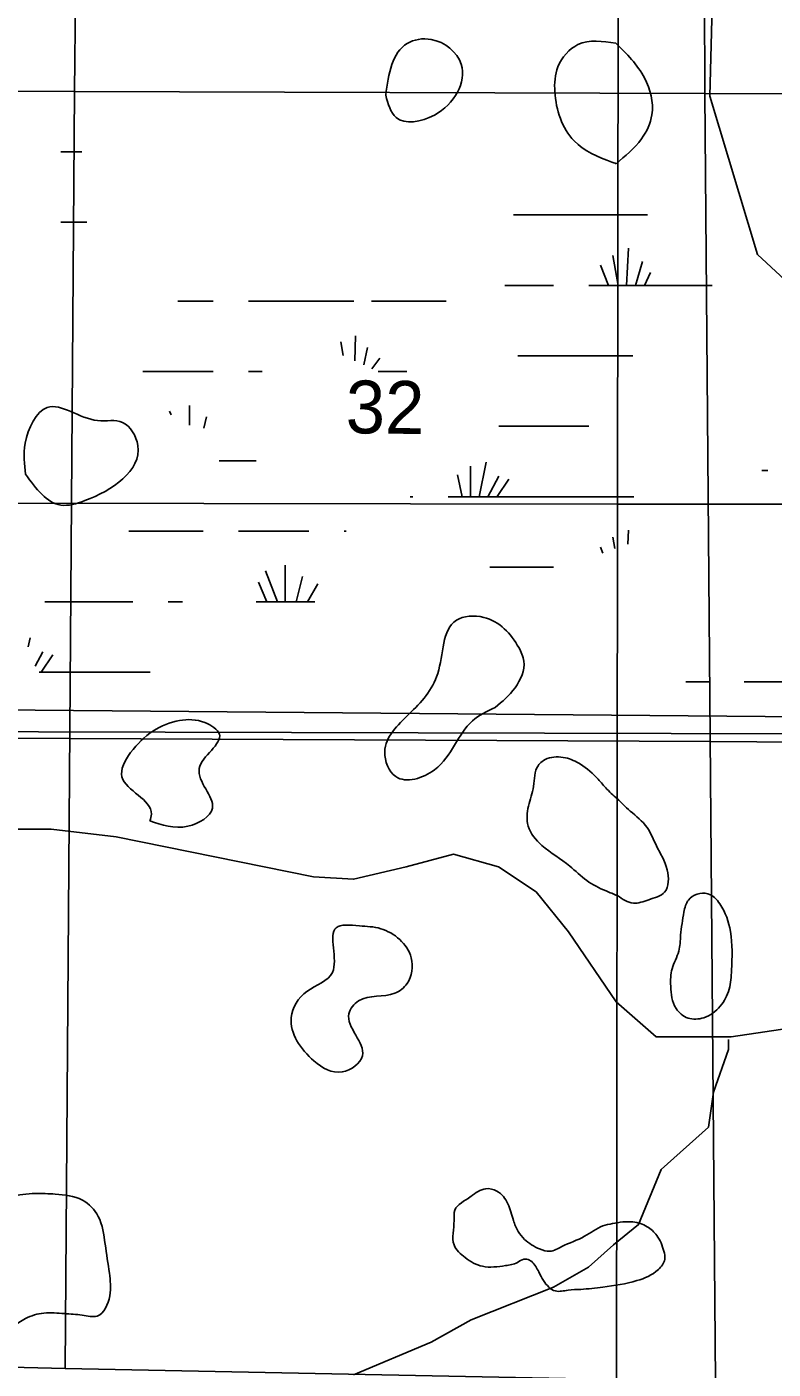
# Model space of a CAD drawing. Extents: x 408847 to 817539, y 923858 to 1151780.
# Drawn here: x 610539 to 616897, y 1007384 to 1018814 of the extents above; entities that cross this region are included whole.
import ezdxf

# ---------------------------------------------------------------- set-up
doc = ezdxf.new("R2010")
doc.units = 0
for name, color, linetype in [('Cities Incorporated Linear Boundaries', 7, 'Continuous'), ('Lakes and Ponds', 7, 'Continuous'), ('Level 43', 7, 'Continuous'), ('Local Roads Paved', 7, 'Continuous'), ('Narrow River Creek and Branch and Slough', 7, 'Continuous'), ('Quad Borders', 7, 'Continuous'), ('Section Lines', 7, 'Continuous'), ('Swamps', 7, 'Continuous')]:
    doc.layers.add(name, color=color, linetype=linetype)

msp = doc.modelspace()

# ---------------------------------------------------------------- linework, layer by layer
at = {"layer": 'Cities Incorporated Linear Boundaries'}
msp.add_line((637441, 1012760), (573420, 1013321), dxfattribs=at)
msp.add_lwpolyline([(605246, 1012826), (637589, 1012739), (637461, 996763)], dxfattribs=at)
at = {"layer": 'Lakes and Ponds'}
msp.add_line((615561, 1012248), (615582, 1012229), dxfattribs=at)
for points in [[(613596, 1018233), (613684, 1018043), (614011, 1018063), (614240, 1018495), (613984, 1018707), (613779, 1018673), (613596, 1018233)], [(615559, 1017649), (615523, 1017662), (615201, 1017844), (615037, 1018260), (615064, 1018474), (615234, 1018663), (615558, 1018675)], [(615558, 1018675), (615801, 1018379), (615864, 1018066), (615775, 1017860), (615559, 1017649)], [(610527, 1015004), (610828, 1014742), (611034, 1014780), (611484, 1015250), (611354, 1015446), (611142, 1015462), (610713, 1015573), (610525, 1015268), (610527, 1015004)], [(614528, 1013019), (614335, 1012905), (614012, 1012488), (613682, 1012430), (613588, 1012641), (613793, 1012961), (614039, 1013307), (614198, 1013762), (614431, 1013786), (614730, 1013528), (614773, 1013413), (614698, 1013186), (614528, 1013019)], [(611587, 1012052), (611911, 1012008), (612120, 1012162), (612008, 1012498), (612179, 1012792), (612056, 1012890), (611840, 1012908), (611423, 1012634), (611349, 1012427), (611600, 1012110), (611587, 1012052)], [(615582, 1012229), (615481, 1012323), (615406, 1012408), (615256, 1012535), (615127, 1012590), (614973, 1012583), (614894, 1012523), (614855, 1012347), (614812, 1012179), (614810, 1012009), (614927, 1011844), (615164, 1011668), (615309, 1011545), (615473, 1011456), (615570, 1011417)], [(615570, 1011417), (615706, 1011352), (615838, 1011382), (615972, 1011446), (615994, 1011636), (615903, 1011841), (615823, 1011997), (615679, 1012137), (615561, 1012248)], [(616137, 1011277), (616109, 1011079), (616093, 1010943), (616036, 1010794), (616024, 1010646), (616070, 1010456), (616172, 1010374), (616306, 1010377), (616446, 1010475), (616522, 1010619), (616543, 1010782), (616533, 1011110), (616443, 1011346), (616340, 1011433), (616175, 1011379), (616137, 1011277)], [(613373, 1011158), (613174, 1011143), (613143, 1010763), (612924, 1010601), (612791, 1010378), (612985, 1010009), (613226, 1009916), (613398, 1010053), (613282, 1010411), (613365, 1010520), (613674, 1010585), (613779, 1010668), (613813, 1010888), (613554, 1011135), (613373, 1011158)], [(614322, 1008856), (614448, 1008921), (614543, 1008901), (614637, 1008793), (614684, 1008651), (614725, 1008557), (614779, 1008489), (614907, 1008408), (614995, 1008388), (615096, 1008428), (615291, 1008516), (615447, 1008604), (615528, 1008624), (615703, 1008638), (615824, 1008597), (615905, 1008523), (615966, 1008388), (615973, 1008320), (615919, 1008233), (615737, 1008138), (615447, 1008084), (615258, 1008064), (615150, 1008057), (615042, 1008050), (614941, 1008138), (614900, 1008212), (614840, 1008300), (614799, 1008320), (614772, 1008320), (614718, 1008293), (614617, 1008266), (614421, 1008260), (614273, 1008334), (614179, 1008442), (614179, 1008651), (614185, 1008739), (614317, 1008852), (614322, 1008856)], [(609791, 1008399), (609740, 1008311), (609683, 1008167), (609672, 1008017), (609749, 1007844), (609984, 1007678), (610142, 1007665), (610302, 1007684), (610527, 1007815), (610683, 1007862), (610859, 1007857), (611011, 1007844), (611139, 1007837), (611245, 1008009), (611242, 1008201), (611206, 1008450), (611147, 1008685), (611012, 1008824), (610780, 1008875), (610612, 1008880), (610400, 1008849), (610169, 1008747), (610041, 1008683), (609912, 1008546), (609791, 1008399)]]:
    msp.add_spline(points, degree=3, dxfattribs=at)
at = {"layer": 'Local Roads Paved'}
for points in [[(617113, 1010298), (616538, 1010213), (616134, 1010213), (615899, 1010213), (615559, 1010511), (615154, 1011108), (614877, 1011449), (614558, 1011662), (614174, 1011769), (613770, 1011662), (613322, 1011556), (612982, 1011577), (611299, 1011918), (610745, 1011982), (610277, 1011982)], [(613322, 1007336), (613983, 1007613), (614323, 1007805), (615026, 1008082), (615324, 1008253), (615537, 1008444), (615750, 1008615), (615942, 1009084), (616347, 1009446), (616389, 1009744), (616517, 1010107), (616517, 1010192)]]:
    msp.add_lwpolyline(points, dxfattribs=at)
at = {"layer": 'Narrow River Creek and Branch and Slough'}
msp.add_lwpolyline([(618154, 1014774), (617887, 1015834), (616765, 1016876), (616357, 1018223), (616454, 1021936)], dxfattribs=at)
at = {"layer": 'Quad Borders'}
for p, q in [((615571, 1014751), (615617, 1060189)), ((574913, 1014812), (615571, 1014751)), ((615526, 969314), (615571, 1014751)), ((615571, 1014751), (656229, 1014731))]:
    msp.add_line(p, q, dxfattribs=at)
at = {"layer": 'Section Lines'}
for p, q in [((616311, 1023460), (616314, 1018246)), ((610984, 1023387), (610946, 1018265)), ((605727, 1018283), (610946, 1018265)), ((610865, 1007391), (610946, 1018265)), ((610946, 1018265), (616314, 1018246)), ((616314, 1018246), (616407, 1007278)), ((605650, 1012780), (610905, 1012754)), ((610905, 1012754), (616361, 1012728)), ((616361, 1012728), (621605, 1012703)), ((605556, 1007500), (610865, 1007391)), ((610865, 1007391), (616407, 1007278))]:
    msp.add_line(p, q, dxfattribs=at)
msp.add_lwpolyline([(616314, 1018248), (621598, 1018242)], dxfattribs=at)
at = {"layer": 'Swamps'}
for p, q in [((615649, 1016613), (615666, 1016929)), ((615493, 1016613), (615427, 1016785)), ((615578, 1016613), (615531, 1016868)), ((615725, 1016613), (615784, 1016817)), ((615802, 1016613), (615851, 1016722)), ((615327, 1016613), (616377, 1016613)), ((611826, 1016479), (612126, 1016479)), ((611826, 1016479), (612126, 1016479)), ((611826, 1016479), (612126, 1016479)), ((612426, 1016479), (613026, 1016479)), ((612426, 1016479), (613026, 1016479)), ((612426, 1016479), (613026, 1016479)), ((613026, 1016479), (613326, 1016479)), ((613026, 1016479), (613326, 1016479)), ((613026, 1016479), (613326, 1016479)), ((611526, 1015879), (612126, 1015879)), ((611526, 1015879), (612126, 1015879)), ((611526, 1015879), (612126, 1015879)), ((614318, 1015072), (614318, 1014813)), ((614451, 1015108), (614392, 1014813)), ((614209, 1014999), (614247, 1014813)), ((614560, 1014987), (614466, 1014812)), ((614644, 1014963), (614545, 1014814)), ((612342, 1014519), (612942, 1014519)), ((612342, 1014519), (612942, 1014519)), ((612572, 1014181), (612675, 1013919)), ((612572, 1014181), (612675, 1013919)), ((612741, 1014230), (612741, 1013919)), ((612741, 1014230), (612741, 1013919)), ((612511, 1014085), (612582, 1013919)), ((612511, 1014085), (612582, 1013919)), ((612886, 1014133), (612832, 1013918)), ((612886, 1014133), (612832, 1013918)), ((610759, 1013468), (610660, 1013319)), ((610759, 1013468), (610660, 1013319)), ((616651, 1013237), (617101, 1013237))]:
    msp.add_line(p, q, dxfattribs=at)
for points in [[(610827, 1017751), (611006, 1017751)], [(610827, 1017751), (611006, 1017751)], [(610827, 1017751), (611006, 1017751)], [(610827, 1017151), (611051, 1017151)], [(610827, 1017151), (611051, 1017151)], [(610827, 1017151), (611051, 1017151)], [(614685, 1017213), (615827, 1017213)], [(614610, 1016613), (615027, 1016613)], [(613476, 1016479), (614110, 1016479)], [(613476, 1016479), (614110, 1016479)], [(613476, 1016479), (614110, 1016479)], [(613233, 1016015), (613214, 1016132)], [(613233, 1016015), (613214, 1016132)], [(613233, 1016015), (613214, 1016132)], [(613334, 1015971), (613338, 1016182)], [(613334, 1015971), (613338, 1016182)], [(613334, 1015971), (613338, 1016182)], [(613411, 1015935), (613442, 1016084)], [(613411, 1015935), (613442, 1016084)], [(613411, 1015935), (613442, 1016084)], [(613479, 1015903), (613545, 1015992)], [(613479, 1015903), (613545, 1015992)], [(613479, 1015903), (613545, 1015992)], [(614721, 1016013), (615702, 1016013)], [(612426, 1015879), (612545, 1015879)], [(612426, 1015879), (612545, 1015879)], [(612426, 1015879), (612545, 1015879)], [(613533, 1015879), (613776, 1015879)], [(613533, 1015879), (613776, 1015879)], [(613533, 1015879), (613776, 1015879)], [(611755, 1015541), (611767, 1015511)], [(611755, 1015541), (611767, 1015511)], [(611755, 1015541), (611767, 1015511)], [(611924, 1015590), (611924, 1015423)], [(611924, 1015590), (611924, 1015423)], [(611924, 1015590), (611924, 1015423)], [(612069, 1015493), (612046, 1015397)], [(612069, 1015493), (612046, 1015397)], [(612069, 1015493), (612046, 1015397)], [(614561, 1015413), (615327, 1015413)], [(612177, 1015119), (612492, 1015119)], [(612177, 1015119), (612492, 1015119)], [(616800, 1015037), (616851, 1015037)], [(613805, 1014813), (613827, 1014813)], [(614127, 1014813), (615711, 1014813)], [(611408, 1014519), (612042, 1014519)], [(611408, 1014519), (612042, 1014519)], [(613242, 1014519), (613260, 1014519)], [(613242, 1014519), (613260, 1014519)], [(615659, 1014408), (615666, 1014529)], [(615447, 1014332), (615427, 1014385)], [(615549, 1014371), (615531, 1014468)], [(614483, 1014213), (615027, 1014213)], [(613019, 1014072), (612929, 1013919)], [(613019, 1014072), (612929, 1013919)], [(610692, 1013919), (611442, 1013919)], [(610692, 1013919), (611442, 1013919)], [(611742, 1013919), (611864, 1013919)], [(611742, 1013919), (611864, 1013919)], [(612492, 1013919), (612991, 1013919)], [(612492, 1013919), (612991, 1013919)], [(610566, 1013613), (610550, 1013535)], [(610566, 1013613), (610550, 1013535)], [(610675, 1013493), (610609, 1013370)], [(610675, 1013493), (610609, 1013370)], [(610644, 1013319), (611590, 1013319)], [(610644, 1013319), (611590, 1013319)], [(616152, 1013237), (616351, 1013237)]]:
    msp.add_lwpolyline(points, dxfattribs=at)

# ---------------------------------------------------------------- texts
at = {"layer": 'Level 43'}
msp.add_text('32', height=450, rotation=359.379, dxfattribs=at).set_placement((613254, 1015354))

doc.saveas('drawing.dxf')
